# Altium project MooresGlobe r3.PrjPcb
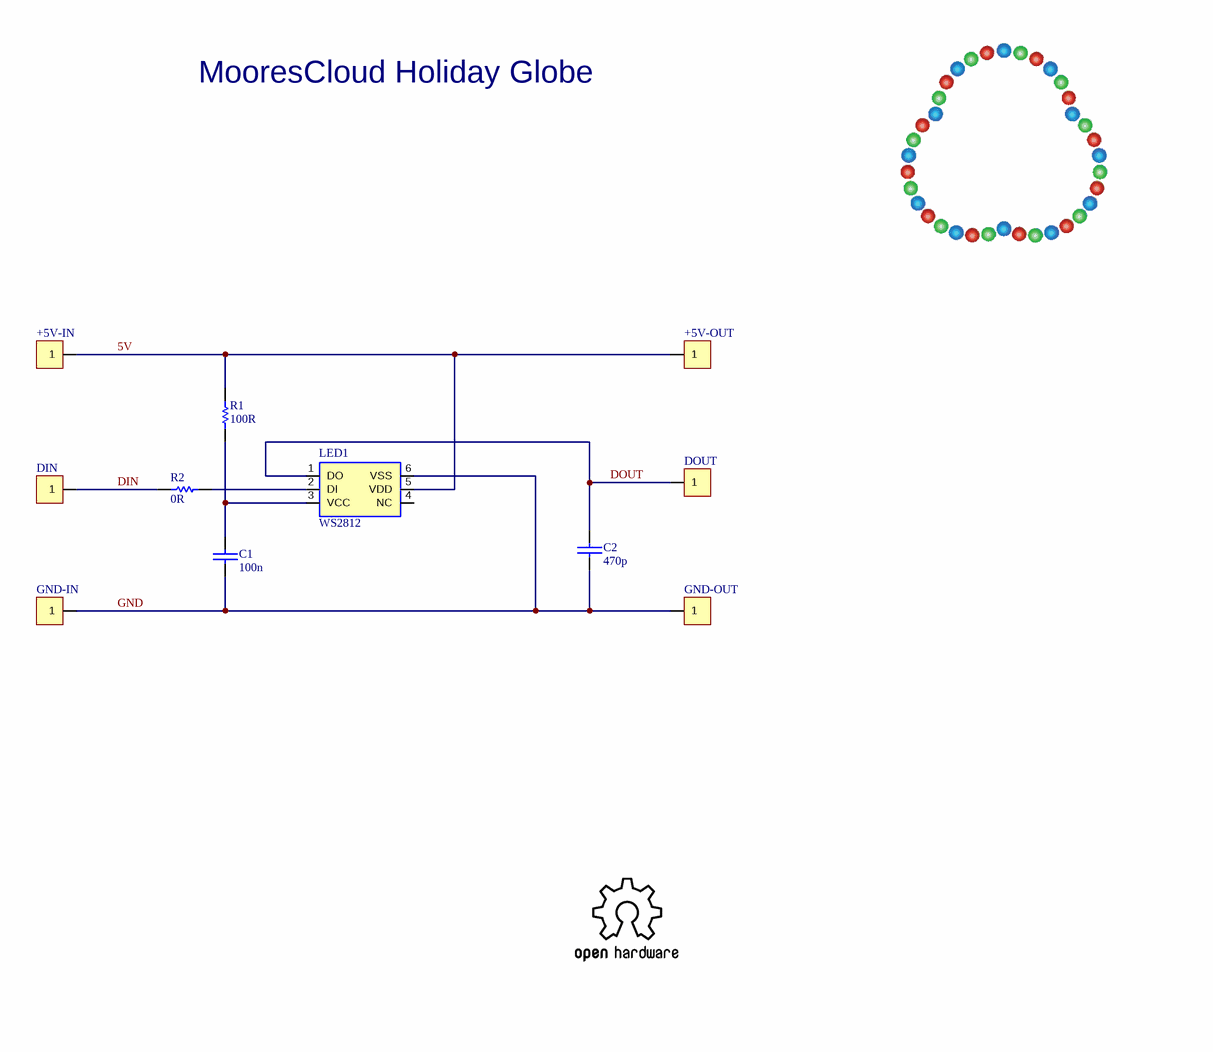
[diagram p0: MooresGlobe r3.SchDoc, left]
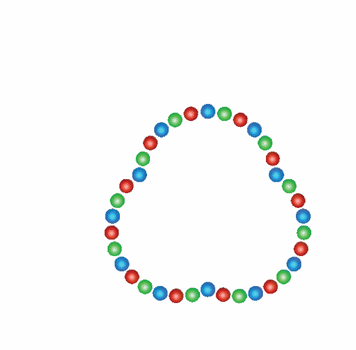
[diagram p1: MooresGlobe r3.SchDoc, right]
1 sheet, 11 parts. Net scope: global (net labels, ports and power ports of the same name join across sheets).
Board files: MooresGlobe r3.PcbDoc, MooresGlobe r3 Panel 10x10.PcbDoc, MooresGlobe r3 Panel 10x10 (no embed).PcbDoc

## Sheet MooresGlobe r3.SchDoc: MooresGlobe for Holiday
size A4; DrawnBy: KJM; Organization: MooresCloud; Revision: 3; SheetNumber: 1; SheetTotal: 1

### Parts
+5V-IN  +5V  [Solder Pad]  (value not drawn)  (no BOM)
+5V-OUT  +5V  [Solder Pad]  (value not drawn)  (no BOM)
C1  100n  [ARA_0603]
C2  470p  [ARA_0603]
DIN  DIN  [Solder Pad]  (value not drawn)  (no BOM)
DOUT  DOUT  [Solder Pad]  (value not drawn)  (no BOM)
GND-IN  GND  [Solder Pad]  (value not drawn)  (no BOM)
GND-OUT  GND  [Solder Pad]  (value not drawn)  (no BOM)
LED1  WS2812  [PLCC6-IPC]
R1  100R  [ARA_0603]
R2  0R  [ARA_0603]

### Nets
5V: +5V-IN.1 +5V-OUT.1 LED1.5(VDD) R1.1
DIN: DIN.1 R2.2
DOUT: C2.1 DOUT.1 LED1.1(DO)
GND: C1.2 C2.2 GND-IN.1 GND-OUT.1 LED1.6(VSS)
NetC1_1: C1.1 LED1.3(VCC) R1.2
NetLED1_2: LED1.2(DI) R2.1

Not connected (* = marked no-connect by the designer): LED1 4(NC)

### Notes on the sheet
- MooresCloud Holiday Globe

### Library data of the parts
+5V-IN +5V-OUT DIN DOUT GND-IN GND-OUT = Solder Pad
C1 = CAP: Capacitor Ceramic 100n 50V Y5V 0603; 1.Manufacturer: Yageo; 4.CatNo: 311-1343-2-ND; 2.MfgNo: CC0603ZRY5V9BB104; 9.UnitCost: 0.00206
C2 = CAP: Capacitor Ceramic 470p 50V NPO 0603; 1.Manufacturer: Yageo; 4.CatNo: 311-1520-2-ND; 2.MfgNo: CC0603JRNPO9BN471; 9.UnitCost: 0.00526
LED1 = WS2812: WorldSemi WS2812 Smart RGB LED; 9.UnitCost: 0.15
R1 = Res Semi: Resistor 100R 0.1W 5% 0603; 1.Manufacturer: Yageo; 4.CatNo: 311-100GRTR-ND; 2.MfgNo: RC0603JR-07100RL; 9.UnitCost: 0.00092
R2 = Res Semi: Resistor 100R 0.1W 5% 0603; 1.Manufacturer: Yageo; 4.CatNo: 311-0.0GRTR-ND; 2.MfgNo: RC0603JR-070RL; 9.UnitCost: 0.00092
